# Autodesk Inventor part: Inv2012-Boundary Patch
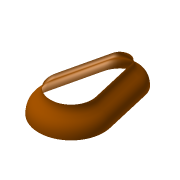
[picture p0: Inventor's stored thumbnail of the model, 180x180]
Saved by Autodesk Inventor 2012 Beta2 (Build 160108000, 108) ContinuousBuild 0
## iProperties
Created: 2011-02
Part Number: Inv2012-Boundary Patch
Material: Default
Document SubType Name: Modeling
Designer: ehttln
Density: 1 g/cm^3
Author: ehttln
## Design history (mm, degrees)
sketch "Sketch1"
  geometry: L1 (-14.61, 78.4)-(-31.167, 7.253); L2 (31.167, 7.253)-(14.61, 78.4); A1 r 32 centre (0, 0) between (-31.167, 7.253) and (31.167, 7.253); A2 r 15 centre (0, 75) between (14.61, 78.4) and (-14.61, 78.4); 1 further point
  constraints: 4 end point, 4 point on circle, 4 tangent, 2 centre point, 2 coincident, 1 vertical alignment
  dimensions: "d5" = 32 radius of A1; "d6" = 15 radius of A2; "d7" = 75 distance of A2.centre A1.centre
workplane "Work Plane1"
sketch "Sketch3"
  geometry: L1 (-14.61, 78.4)-(-31.167, 7.253) reference; L2 (31.167, 7.253)-(14.61, 78.4) reference; L3 (-32.141, 82.48)-(-48.699, 11.333); L4 (48.699, 11.333)-(32.141, 82.48); A1 r 15 centre (0, 75) between (14.61, 78.4) and (-14.61, 78.4) reference; A2 r 32 centre (0, 0) between (-31.167, 7.253) and (31.167, 7.253) reference; A3 r 33 centre (0, 75) between (32.141, 82.48) and (-32.141, 82.48); A4 r 50 centre (0, 0) between (-48.699, 11.333) and (48.699, 11.333); 2 further points
  constraints: 4 end point, 4 point on circle, 2 centre point, 3 other
  dimensions: "d9" = 50 radius of A4
feature "LoftSrf1" dims "d13" = 50, "d14" = 90 deg, "d15" = 70, "d16" = 90 deg
patch "Boundary Patch1" dims "d17" = 0, "d18" = 0
patch "Boundary Patch3" dims "d21" = 0, "d22" = 0
patch "Boundary Patch4" dims "d23" = 0, "d24" = 0
body "Srf2"
body "Srf3"
body "Srf5"
body "Srf6"
other parameters: "d8" = -35
